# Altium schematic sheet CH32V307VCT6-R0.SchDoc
size 332 x 281 mm
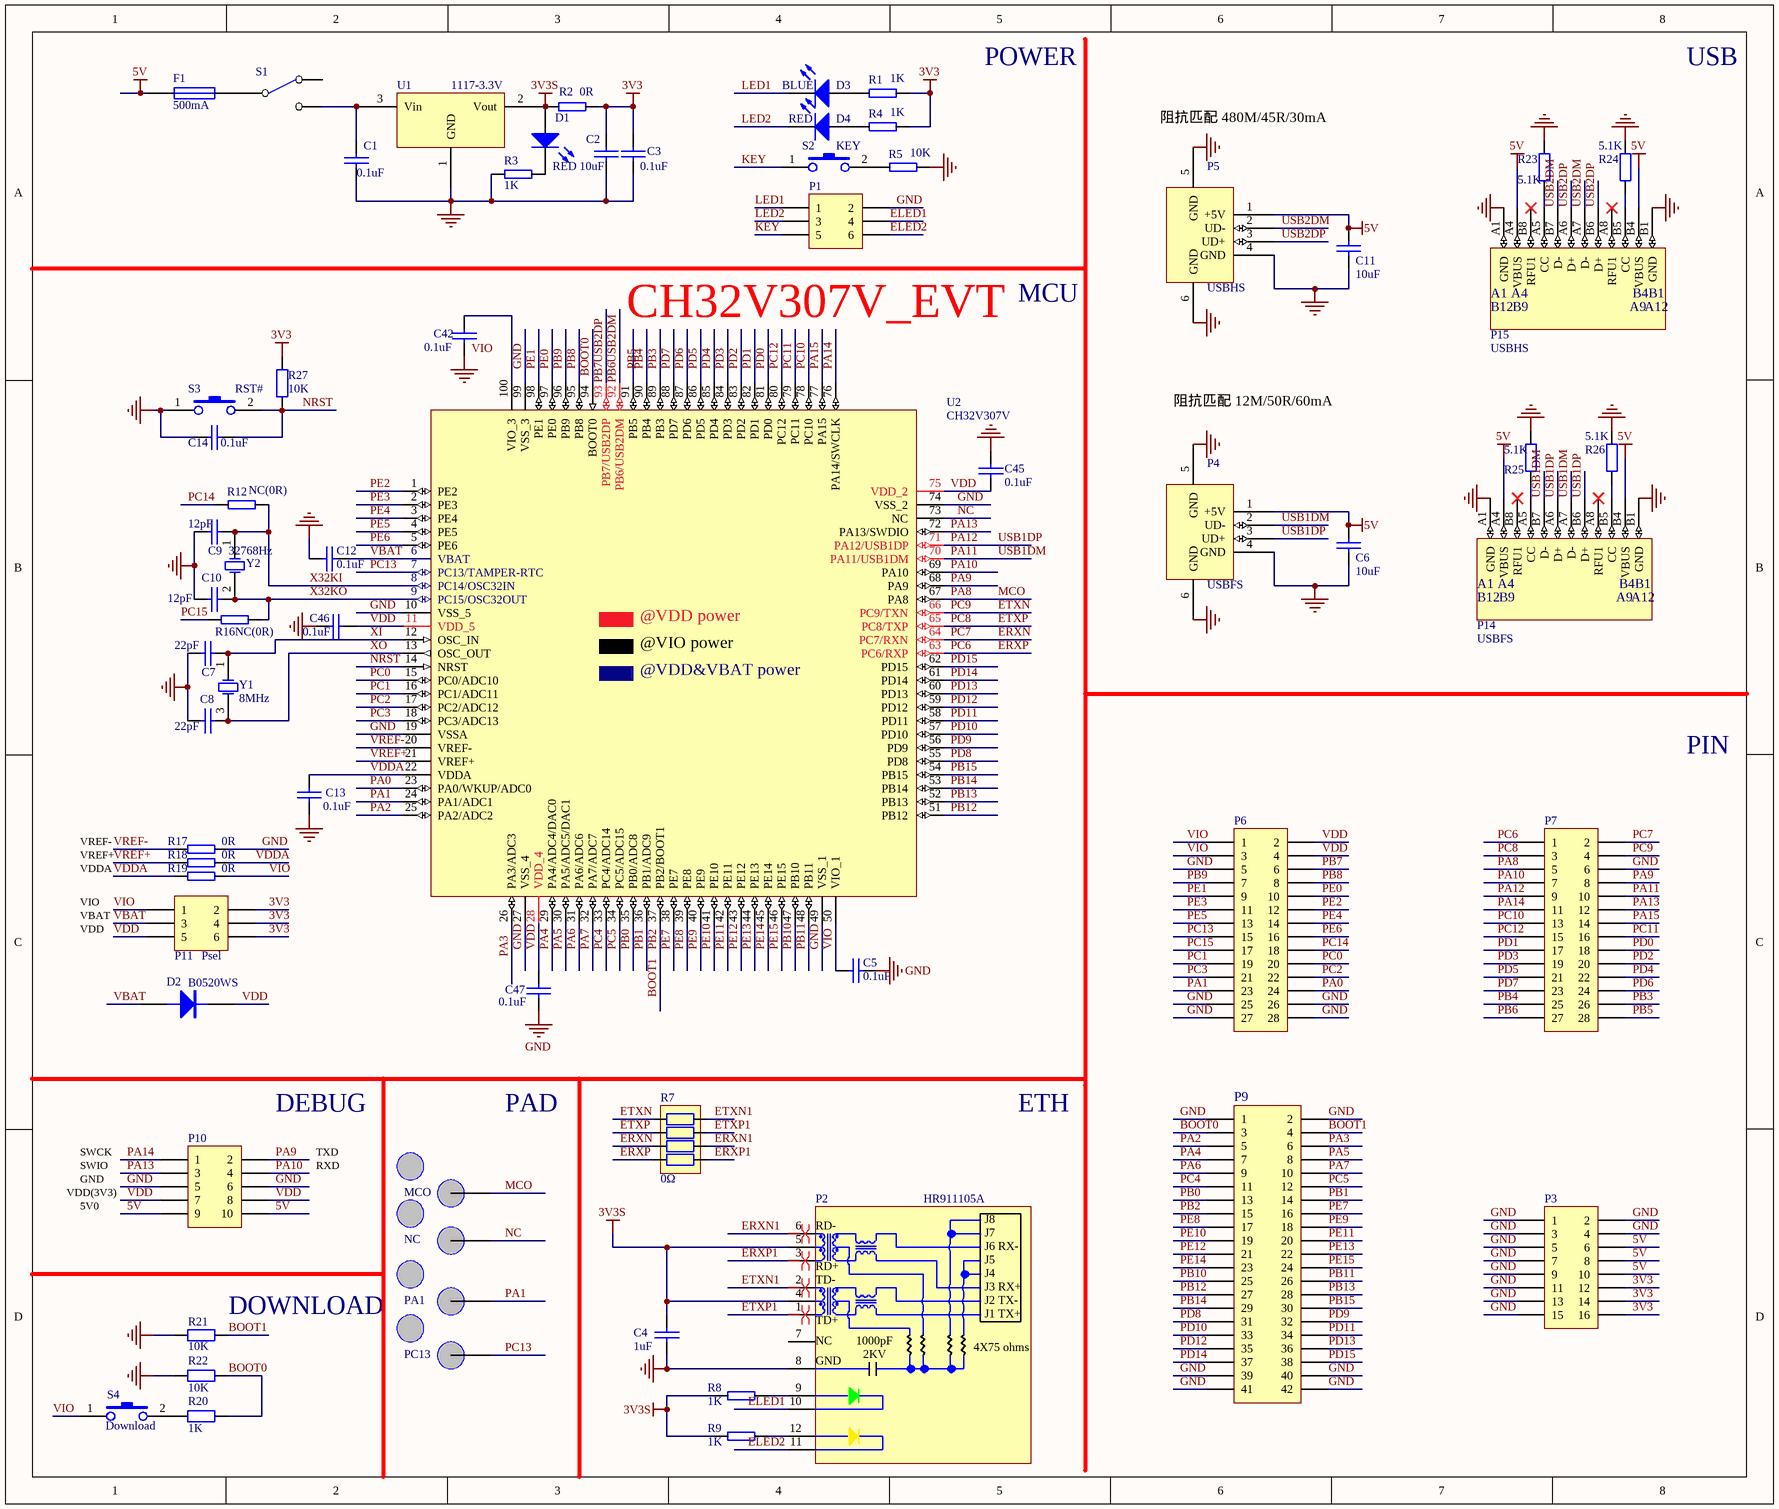
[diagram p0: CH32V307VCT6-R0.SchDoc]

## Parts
C1  0.1uF  [0603_C]
C2  10uF  [3216_C]
C3  0.1uF  [0603_C]
C4  1uF  [0603_C]
C5  0.1uF  [0603_C]
C6  10uF  [3216_C]
C7  22pF  [0603_C]
C8  22pF  [0603_C]
C9  12pF  [0603_C]
C10  12pF  [0603_C]
C11  10uF  [3216_C]
C12  0.1uF  [0603_C]
C13  0.1uF  [0603_C]
C14  0.1uF  [0603_C]
C42  0.1uF  [0603_C]
C45  0.1uF  [0603_C]
C46  0.1uF  [0603_C]
C47  0.1uF  [0603_C]
D1  RED  [0603+]
D2  B0520WS  [SOD-323]
D3  BLUE  [0603+]
D4  RED  [0603+]
F1  500mA  [0805]
MCO  Testpoint  [TESTPOINT1]  (value not drawn)
NC  Testpoint  [TESTPOINT1]  (value not drawn)
P1  IO  [IDC6-2.54mm]  (value not drawn)
P2  HR911105A  [HR911105A]
P3  Ppin  [IDC16-2.54mm]  (value not drawn)
P4  USBFS  [USBAF]
P5  USBHS  [USBAF]
P6  HEADER 14x2  [IDC28-2.54MM]  (value not drawn)
P7  HEADER 14x2  [IDC28-2.54MM]  (value not drawn)
P9  HEADER 21x2  [IDC42-2.54MM]  (value not drawn)
P10  LINK  [IDC10-2.54mm]  (value not drawn)
P11  Psel  [IDC6-2.54mm]
P14  USBFS  [TYPE-C-Receptacle-2.0]
P15  USBHS  [TYPE-C-Receptacle-2.0]
PA1  Testpoint  [TESTPOINT1]  (value not drawn)
PC13  Testpoint  [TESTPOINT1]  (value not drawn)
R1  1K  [0603]
R2  0R  [0603]
R3  1K  [0603]
R4  1K  [0603]
R5  10K  [0603]
R7  0Ω  [RCA-8P4R-0603]
R8  1K  [0603]
R9  1K  [0603]
R12  NC(0R)  [0603]
R16  NC(0R)  [0603]
R17  0R  [0603]
R18  0R  [0603]
R19  0R  [0603]
R20  1K  [0603]
R21  10K  [0603]
R22  10K  [0603]
R23  5.1K  [0603]
R24  5.1K  [0603]
R25  5.1K  [0603]
R26  5.1K  [0603]
R27  10K  [0603]
S1  SW SPDT  [KEY_B]  (value not drawn)
S2  KEY  [SMD_6.1x3.65x2.5mm-KEY]
S3  RST#  [SMD_6.1x3.65x2.5mm-KEY]
S4  Download  [SMD_6.1x3.65x2.5mm-KEY]
U1  1117-3.3V  [SOT-223]
U2  CH32V307V  [LQFP100]
Y1  8MHz  [XT3225]
Y2  32768Hz  [FC-135]

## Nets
3V3: C2.1 C3.1 P3.12 P3.14 P3.16 P11.2 P11.4 P11.6 R1.1 R2.1 R4.1 R27.2
3V3S: C4.2 D1.1(A) P2.4 P2.5 R2.2 R8.1 R9.1 U1.2(Vout)
5V: C6.1 C11.1 F1.1 P3.6 P3.8 P3.10 P4.1(+5V) P5.1(+5V) P10.9 P10.10 P14.A4(VBUS) P14.B4(VBUS) P15.A4(VBUS) P15.B4(VBUS)
GND: C1.2 C2.2 C3.2 C4.1 C5.2 C6.2 C7.1 C8.1 C9.1 C10.1 C11.2 C12.1 C13.2 C14.1 C42.1 C45.2 C46.2 C47.1 P1.2 P2.8 P3.1 P3.2 P3.3 P3.4 P3.5 P3.7 P3.9 P3.11 P3.13 P3.15 P4.4(GND) P4.5(GND) P4.6(GND) P5.4(GND) P5.5(GND) P5.6(GND) P6.5 P6.25 P6.26 P6.27 P6.28 P7.6 P9.1 P9.2 P9.39 P9.40 P9.41 P9.42 P10.5 P10.6 P14.A1(GND) P14.B1(GND) P15.A1(GND) P15.B1(GND) R3.2 R5.1 R17.1 R21.2 R22.2 R23.2 R24.2 R25.2 R26.2 S3.1 U1.1(GND) U2.10(VSS_5) U2.19(VSSA) U2.27(VSS_4) U2.49(VSS_1) U2.74(VSS_2) U2.99(VSS_3)
BOOT0: P9.3 R20.1 R22.1 U2.94(BOOT0)
BOOT1: P9.4 P9.15 R21.1 U2.37(PB2/BOOT1)  [also labelled PB2]
ELED1: P1.4 P2.10
ELED2: P1.6 P2.11
ERXN: P7.2 R7.3 U2.64(PC7/RXN)  [also labelled PC7]
ERXN1: P2.6 R7.6
ERXP: P7.1 R7.4 U2.63(PC6/RXP)  [also labelled PC6]
ERXP1: P2.3 R7.5
ETXN: P7.4 R7.1 U2.66(PC9/TXN)  [also labelled PC9]
ETXN1: P2.2 R7.8
ETXP: P7.3 R7.2 U2.65(PC8/TXP)  [also labelled PC8]
ETXP1: P2.1 R7.7
KEY: P1.5 S2.1
LED1: D3.2(K) P1.1
LED2: D4.2(K) P1.3
MCO: MCO.1(point) P7.5 U2.67(PA8)  [also labelled PA8]
NC: NC.1(point) U2.73(NC)
NRST: C14.2 R27.1 S3.2 U2.14(NRST)
PA0: P6.24 U2.23(PA0/WKUP/ADC0)
PA1: P6.23 PA1.1(point) U2.24(PA1/ADC1)
PA2: P9.5 U2.25(PA2/ADC2)
PA3: P9.6 U2.26(PA3/ADC3)
PA4: P9.7 U2.29(PA4/ADC4/DAC0)
PA5: P9.8 U2.30(PA5/ADC5/DAC1)
PA6: P9.9 U2.31(PA6/ADC6)
PA7: P9.10 U2.32(PA7/ADC7)
PA9: P7.8 P10.2 U2.68(PA9)
PA10: P7.7 P10.4 U2.69(PA10)
PA11: P4.2(UD-) P7.10 P14.A7(D-) P14.B7(D-) U2.70(PA11/USB1DM)  [also labelled USB1DM]
PA12: P4.3(UD+) P7.9 P14.A6(D+) P14.B6(D+) U2.71(PA12/USB1DP)  [also labelled USB1DP]
PA13: P7.12 P10.3 U2.72(PA13/SWDIO)
PA14: P7.11 P10.1 U2.76(PA14/SWCLK)
PA15: P7.14 U2.77(PA15)
PB0: P9.13 U2.35(PB0/ADC8)
PB1: P9.14 U2.36(PB1/ADC9)
PB3: P7.26 U2.89(PB3)
PB4: P7.25 U2.90(PB4)
PB5: P7.28
PB6: P5.2(UD-) P7.27 P15.A7(D-) P15.B7(D-) U2.92(PB6/USB2DM)  [also labelled USB2DM]
PB7: P5.3(UD+) P6.6 P15.A6(D+) P15.B6(D+) U2.93(PB7/USB2DP)  [also labelled USB2DP]
PB8: P6.8 U2.95(PB8)
PB9: P6.7 U2.96(PB9)
PB10: P9.25 U2.47(PB10)
PB11: P9.26 U2.48(PB11)
PB12: P9.27 U2.51(PB12)
PB13: P9.28 U2.52(PB13)
PB14: P9.29 U2.53(PB14)
PB15: P9.30 U2.54(PB15)
PC0: P6.20 U2.15(PC0/ADC10)
PC1: P6.19 U2.16(PC1/ADC11)
PC2: P6.22 U2.17(PC2/ADC12)
PC3: P6.21 U2.18(PC3/ADC13)
PC4: P9.11 U2.33(PC4/ADC14)
PC5: P9.12 U2.34(PC5/ADC15)
PC10: P7.13 U2.78(PC10)
PC11: P7.16 U2.79(PC11)
PC12: P7.15 U2.80(PC12)
PC13: P6.15 PC13.1(point) U2.7(PC13/TAMPER-RTC)
PC14: P6.18 R12.1
PC15: P6.17 R16.1
PD0: P7.18 U2.81(PD0)
PD1: P7.17 U2.82(PD1)
PD2: P7.20 U2.83(PD2)
PD3: P7.19 U2.84(PD3)
PD4: P7.22 U2.85(PD4)
PD5: P7.21 U2.86(PD5)
PD6: P7.24 U2.87(PD6)
PD7: P7.23 U2.88(PD7)
PD8: P9.31 U2.55(PD8)
PD9: P9.32 U2.56(PD9)
PD10: P9.33 U2.57(PD10)
PD11: P9.34 U2.58(PD11)
PD12: P9.35 U2.59(PD12)
PD13: P9.36 U2.60(PD13)
PD14: P9.37 U2.61(PD14)
PD15: P9.38 U2.62(PD15)
PE0: P6.10 U2.97(PE0)
PE1: P6.9 U2.98(PE1)
PE2: P6.12 U2.1(PE2)
PE3: P6.11 U2.2(PE3)
PE4: P6.14 U2.3(PE4)
PE5: P6.13 U2.4(PE5)
PE6: P6.16 U2.5(PE6)
PE7: P9.16 U2.38(PE7)
PE8: P9.17 U2.39(PE8)
PE9: P9.18 U2.40(PE9)
PE10: P9.19 U2.41(PE10)
PE11: P9.20 U2.42(PE11)
PE12: P9.21 U2.43(PE12)
PE13: P9.22 U2.44(PE13)
PE14: P9.23 U2.45(PE14)
PE15: P9.24 U2.46(PE15)
VBAT: C12.2 D2.1(A) P11.3 U2.6(VBAT)
VDD: C45.1 C46.1 C47.2 D2.2(K) P6.2 P6.4 P10.7 P10.8 P11.5 U2.11(VDD_5) U2.28(VDD_4) U2.75(VDD_2)
VDDA: C13.1 R18.1 R19.2 U2.22(VDDA)
VIO: C5.1 P6.1 P6.3 P11.1 R19.1 S4.1 U2.50(VIO_1)
VREF+: R18.2 U2.21(VREF+)
VREF-: R17.2 U2.20(VREF-)
X32KI: C9.2 R12.2 U2.8(PC14/OSC32IN) Y2.1(OSC1)
X32KO: C10.2 R16.2 U2.9(PC15/OSC32OUT) Y2.2(OSC2)
XI: C7.2 U2.12(OSC_IN) Y1.1(OSC1)
XO: C8.2 U2.13(OSC_OUT) Y1.3(OSC2)
NetC1_1: C1.1 S1.2(NC) U1.3(Vin)
NetC42_2: C42.2 U2.100(VIO_3)
NetD1_2: D1.2(K) R3.1
NetD3_1: D3.1(A) R1.2
NetD4_1: D4.1(A) R4.2
NetF1_2: F1.2 S1.1(COMMON)
NetP2_9: P2.9 R8.2
NetP2_12: P2.12 R9.2
NetP14_A5: P14.A5(CC) R25.1
NetP14_B5: P14.B5(CC) R26.1
NetP15_A5: P15.A5(CC) R23.1
NetP15_B5: P15.B5(CC) R24.1
NetR5_2: R5.2 S2.2
NetR20_2: R20.2 S4.2

Not connected (* = marked no-connect by the designer): P2 7; P14 A8(RFU1)* B8(RFU1)*; P15 A8(RFU1)* B8(RFU1)*; S1 3(NO); U2 91(PB5)

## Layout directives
differential pair: ERXN1, ERXP1, ETXN1, ETXP1

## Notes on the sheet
- POWER
- USB
- 阻抗匹配 480M/45R/30mA
- MCU
- (near P1) CH32V307V_EVT
- 阻抗匹配 12M/50R/60mA
- PIN
- VREF-
- VREF+
- VDDA
- VIO
- VBAT
- VDD
- (near P10) DEBUG
- PAD
- ETH
- SWCK
- SWIO
- GND
- TXD
- RXD
- VDD(3V3)
- 5V0
- (near R21) DOWNLOAD
- Labels drawn without touching a wire or pin: PB5, VIO

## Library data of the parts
C1-C14 C42 C45-C47 = CAP: Capacitor
D1 D3 D4 = LED0: Typical INFRARED GaAs LED
D2 = DIODE
F1 = FUSE1: Fuse
MCO NC PA1 PC13 = Testpoint: 测试点
P1 P11 = Header 3X2H: Header, 3-Pin, Dual row, Right Angle
P3 = Header 8X2H: Header, 8-Pin, Dual row, Right Angle
P4 P5 = USB: USB Port
P6 P7 = HEADER 14x2: Header, 14-Pin, Dual row
P9 = HEADER 21x2: Header, 21-Pin, Dual row
P10 = Header 5X2H: Header, 5-Pin, Dual row, Right Angle
P14 P15 = TYPE-C1
R1-R5 R8 R9 R12 R16 = RES
R7 = R-8P4R: 贴片网络排阻; 版权归属: 源创客
R17-R19 = R
R20-R27 = Res2: Resistor
S2-S4 = KEY1
U2 = CH32V307V: RISC-V FPU HD-MCU, 144MHz, USB_480M, USB OTG, 1000M Ethernet MAC, 2*CAN, FSMC+DVP
Y1 Y2 = XTAL: Crystal Oscillator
